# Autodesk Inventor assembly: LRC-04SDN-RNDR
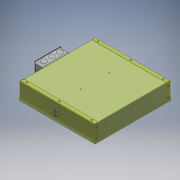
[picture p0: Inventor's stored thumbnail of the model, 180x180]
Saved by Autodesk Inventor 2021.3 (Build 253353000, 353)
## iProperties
Part Number: LRC-04SDN-RNDR
Document SubType Name: Assembly
Designer: JChurch
Author: JChurch
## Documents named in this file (5)
- X:\Revit Files\0000-Un-Zipped\COB\LRC-04SDN-RND\LRC-04SDN-RNDR.iam
- X:\INVENTOR\830\830520-00-00.ipt
- X:\INVENTOR\885\885000-00-00.iam
- X:\INVENTOR\750\750031-00-XX.iam
- X:\INVENTOR\725\725377-00-00.ipt
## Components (4 placed, 4 different names)
1. 830520-00-00:1 — Mate:1, Mate:2, Mate:3, Mate:4, Mate:5, Angle:1, Insert:2
2. 885000-00-00:1 [sub-assembly] — Mate:4, Mate:5, Angle:1
3. 750031-00-XX:1 [sub-assembly] — Insert:1, Insert:2
4. 725377-00-00:1 — Insert:1
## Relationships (8: Mate 5, Insert 2, Angle 1)
- Mate:1: 830520-00-00:1
- Mate:2: 830520-00-00:1
- Mate:3: 830520-00-00:1
- Mate:4: 830520-00-00:1 ↔ 885000-00-00:1
- Mate:5: 830520-00-00:1 ↔ 885000-00-00:1
- Angle:1: 830520-00-00:1 ↔ 885000-00-00:1
- Insert:1: 750031-00-XX:1 ↔ 725377-00-00:1
- Insert:2: 830520-00-00:1 ↔ 750031-00-XX:1
